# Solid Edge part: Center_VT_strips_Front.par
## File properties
Author: haileyy
Template: ansi part.par
Last saved by: haileyy
Revision: 3
Application: Solid Edge
Accuracy: 0.990
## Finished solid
Body 1: solid body, 6 faces, 12 edges, 8 vertices.
  Faces by surface: plane 6
  Edges by curve: line 12
Bounding box of the edges (mm): 6.198 x 3.302 x 234.950, from (-51.1508, 20.2474, -234.95) to (-44.9532, 23.5494, 0).
Planar faces by outward normal: +x 1, +y 1, +z 1, -x 1, -y 1, -z 1
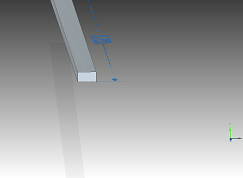
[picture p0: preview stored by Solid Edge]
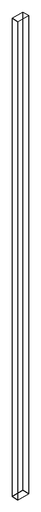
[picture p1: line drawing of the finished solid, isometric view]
